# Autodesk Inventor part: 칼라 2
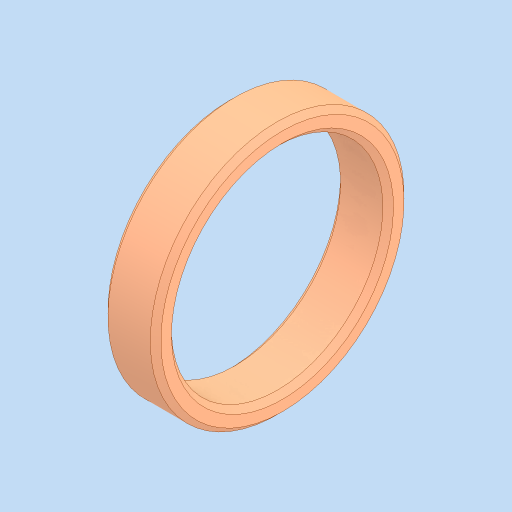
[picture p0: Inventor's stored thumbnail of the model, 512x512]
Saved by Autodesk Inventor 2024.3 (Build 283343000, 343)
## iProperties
Created: 2025-11
Part Number: 칼라 2
Material: 강철, 연강
Document SubType Name: Modeling
Designer: PC2-02
Density: 7.85 g/cm^3
Appearance: 기본값
Author: jhkim
Sending System: Autodesk Inventor 2026
Preprocessor: ST-DEVELOPER v20.1
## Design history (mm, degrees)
node "칼라 21"
node "솔리드2"
node "솔리드1"
